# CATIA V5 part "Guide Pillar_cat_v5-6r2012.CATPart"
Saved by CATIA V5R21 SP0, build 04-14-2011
Part number: Guide Pillar
Bounding box of the stored display mesh (mm): x 82.5 to 107.5, y 17.69 to 42.31, z 0 to 200
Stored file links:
  D:\CATIA V5R21 E-RESOURCES\CATIA-V5R21\catia-v5r21-Tut\c12-catia-v5r21-tut\c12-catia-v5r21-tut02\Guide Pillar_cat_v5r21.CATPart
  D:\CATIA V5R21 E-RESOURCES\CATIA-V5R21\catia-v5r21-Tut\c12-catia-v5r21-tut\c12-catia-v5r21-tut02\Assembly.CATProduct
  D:\CATIA V5R21 E-RESOURCES\CATIA-V5R21\catia-v5r21-Tut\c12-catia-v5r21-tut\c12-catia-v5r21-tut02\Bottom Plate.CATPart
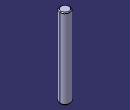
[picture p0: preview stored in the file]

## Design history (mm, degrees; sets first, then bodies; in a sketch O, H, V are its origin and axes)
Set1
  DatumSurface1: linked copy from another document
  DatumCurve1: linked copy from another document
Body1 (main body)
  Sketch1 on face of DatumSurface1, origin (0, 0, 0), H (1, 0, 0), V (0, 1, 0)
    projected circle E1 centre (95, 30) radius 12.5 from edge of DatumCurve1
  Pad1: profile Sketch1, direction (0, 0, 1), length 200
  Chamfer1: length 2, angle 45, on edge [face of Pad1 | face of Pad1] (x2)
